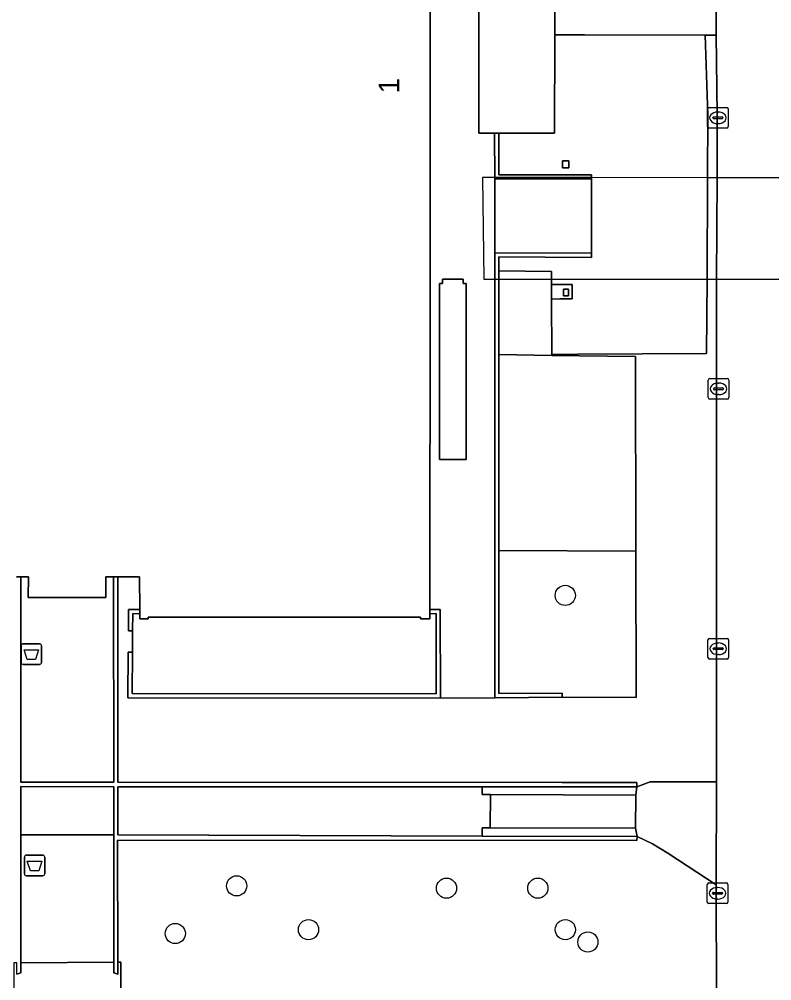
# Model space of a CAD drawing. Extents: x 161477 to 163040, y 383680 to 384871.
# Drawn here: x 161774.1 to 161810.58, y 384278.53 to 384325.12 of the extents above; entities that cross this region are included whole.
import ezdxf

# ---------------------------------------------------------------- set-up
doc = ezdxf.new("R2010")
doc.units = 0
for name, color, linetype in [('IMGEO_Afvalbak', 7, 'Continuous'), ('IMGEO_Boom', 7, 'Continuous'), ('IMGEO_Dek', 7, 'Continuous'), ('IMGEO_Erf', 7, 'Continuous'), ('IMGEO_Groenvoorziening', 7, 'Continuous'), ('IMGEO_Kolk', 7, 'Continuous'), ('IMGEO_Muur', 7, 'Continuous'), ('IMGEO_Pand', 7, 'Continuous'), ('IMGEO_Pand_nummerreeks', 7, 'Continuous'), ('IMGEO_Parkeervlak_open', 7, 'Continuous'), ('IMGEO_Pijler', 7, 'Continuous'), ('IMGEO_Rijbaan_lokaal_open', 7, 'Continuous'), ('IMGEO_Voetpad_gesloten', 7, 'Continuous'), ('IMGEO_Voetpad_op_trap', 7, 'Continuous'), ('IMGEO_Voetpad_open', 7, 'Continuous')]:
    doc.layers.add(name, color=color, linetype=linetype)

msp = doc.modelspace()

# ---------------------------------------------------------------- linework, layer by layer
at = {"layer": 'IMGEO_Afvalbak'}
for p, q in [((161774.285, 384294.86), (161775.075, 384294.86)), ((161775.075, 384294.86), (161774.285, 384294.86)), ((161774.185, 384293.96), (161774.185, 384294.76)), ((161774.185, 384294.76), (161774.185, 384293.96)), ((161775.175, 384294.76), (161775.175, 384293.96)), ((161775.175, 384293.96), (161775.175, 384294.76)), ((161775.075, 384293.86), (161774.285, 384293.86)), ((161774.285, 384293.86), (161775.075, 384293.86)), ((161774.445, 384284.62), (161775.235, 384284.62)), ((161775.235, 384284.62), (161774.445, 384284.62)), ((161774.345, 384283.72), (161774.345, 384284.52)), ((161774.345, 384284.52), (161774.345, 384283.72)), ((161775.335, 384284.52), (161775.335, 384283.72)), ((161775.335, 384283.72), (161775.335, 384284.52)), ((161775.235, 384283.62), (161774.445, 384283.62)), ((161774.445, 384283.62), (161775.235, 384283.62))]:
    msp.add_line(p, q, dxfattribs=at)
for points in [[(161774.328, 384294.574), (161775.032, 384294.574), (161774.883, 384294.104), (161774.477, 384294.104), (161774.328, 384294.574)], [(161774.488, 384284.334), (161775.192, 384284.334), (161775.043, 384283.864), (161774.637, 384283.864), (161774.488, 384284.334)]]:
    msp.add_lwpolyline(points, dxfattribs=at)
for centre, start, end in [((161774.285, 384294.76), 90, 180), ((161774.285, 384294.76), 90, 180), ((161775.075, 384294.76), 0, 90), ((161775.075, 384294.76), 360, 90), ((161774.285, 384293.96), 180, 270), ((161774.285, 384293.96), 180, 270), ((161775.075, 384293.96), 270, 0), ((161775.075, 384293.96), 270, 0), ((161774.445, 384284.52), 90, 180), ((161774.445, 384284.52), 90, 180), ((161775.235, 384284.52), 0, 90), ((161775.235, 384284.52), 360, 90), ((161774.445, 384283.72), 180, 270), ((161774.445, 384283.72), 180, 270), ((161775.235, 384283.72), 270, 0), ((161775.235, 384283.72), 270, 0)]:
    msp.add_arc(centre, 0.1, start, end, dxfattribs=at)
at = {"layer": 'IMGEO_Boom'}
for centre in [(161800.569, 384297.207), (161784.637, 384283.132), (161794.812, 384283.021), (161799.239, 384283.021), (161781.662, 384280.822), (161788.122, 384281.011), (161800.571, 384281.011), (161801.665, 384280.411)]:
    msp.add_circle(centre, 0.489, dxfattribs=at)
at = {"layer": 'IMGEO_Dek'}
msp.add_lwpolyline([(161859.88, 384317.389), (161855.377, 384317.394), (161817.96, 384317.433), (161817.483, 384317.433), (161815.892, 384317.434), (161810.287, 384317.441), (161807.922, 384317.443), (161801.84, 384317.449), (161797.149, 384317.454), (161796.557, 384317.455), (161796.614, 384312.532), (161797.345, 384312.53), (161799.896, 384312.527), (161807.923, 384312.527), (161808.422, 384312.528), (161810.306, 384312.528), (161815.872, 384312.528), (161817.492, 384312.528), (161817.958, 384312.528), (161855.375, 384312.529), (161859.867, 384312.53)], close=True, dxfattribs=at)
at = {"layer": 'IMGEO_Erf'}
msp.add_lwpolyline([(161794.302, 384296.322), (161794.005, 384296.308), (161794.005, 384296.078), (161793.545, 384296.078), (161793.545, 384296.158), (161780.347, 384296.145), (161780.346, 384296.065), (161779.936, 384296.068), (161779.938, 384296.318), (161779.598, 384296.321), (161779.592, 384295.491), (161779.584, 384294.451), (161779.569, 384292.446), (161794.316, 384292.437)], close=True, dxfattribs=at)
at = {"layer": 'IMGEO_Groenvoorziening'}
msp.add_lwpolyline([(161803.988, 384299.357), (161797.346, 384299.385), (161797.347, 384292.449), (161800.419, 384292.462), (161800.42, 384292.27), (161803.998, 384292.262)], close=True, dxfattribs=at)
msp.add_lwpolyline([(161807.898, 384277.631), (161807.882, 384283.178), (161805.547, 384284.717), (161804.8, 384285.171), (161804.047, 384285.519), (161804.034, 384285.325), (161778.862, 384285.349), (161778.872, 384279.429), (161779.026, 384279.43), (161779.027, 384277.89)], dxfattribs=at)
at = {"layer": 'IMGEO_Kolk'}
for p, q in [((161807.469, 384319.922), (161807.469, 384320.774)), ((161807.544, 384320.848), (161808.396, 384320.848)), ((161807.957, 384320.628), (161807.982, 384320.628)), ((161808.47, 384320.774), (161808.47, 384319.922)), ((161807.728, 384320.342), (161807.728, 384320.354)), ((161808.166, 384320.305), (161807.768, 384320.305)), ((161807.771, 384320.391), (161808.169, 384320.391)), ((161807.98, 384320.068), (161807.955, 384320.068)), ((161808.212, 384320.354), (161808.212, 384320.342)), ((161808.396, 384319.848), (161807.544, 384319.848)), ((161807.499, 384306.789), (161807.499, 384307.641)), ((161807.574, 384307.715), (161808.426, 384307.715)), ((161807.987, 384307.495), (161808.012, 384307.495)), ((161808.5, 384307.641), (161808.5, 384306.789)), ((161807.758, 384307.209), (161807.758, 384307.221)), ((161808.196, 384307.172), (161807.798, 384307.172)), ((161807.801, 384307.258), (161808.199, 384307.258)), ((161808.01, 384306.935), (161807.985, 384306.935)), ((161808.242, 384307.221), (161808.242, 384307.209)), ((161808.426, 384306.715), (161807.574, 384306.715)), ((161807.485, 384294.194), (161807.485, 384295.046)), ((161807.56, 384295.12), (161808.412, 384295.12)), ((161807.973, 384294.9), (161807.998, 384294.9)), ((161808.486, 384295.046), (161808.486, 384294.194)), ((161807.744, 384294.614), (161807.744, 384294.626)), ((161808.182, 384294.577), (161807.784, 384294.577)), ((161807.787, 384294.663), (161808.185, 384294.663)), ((161808.228, 384294.626), (161808.228, 384294.614)), ((161808.412, 384294.12), (161807.56, 384294.12)), ((161807.996, 384294.34), (161807.971, 384294.34)), ((161807.453, 384282.348), (161807.453, 384283.2)), ((161807.528, 384283.274), (161808.38, 384283.274)), ((161808.454, 384283.2), (161808.454, 384282.348)), ((161807.712, 384282.768), (161807.712, 384282.78)), ((161808.15, 384282.731), (161807.752, 384282.731)), ((161807.755, 384282.817), (161808.153, 384282.817)), ((161807.941, 384283.054), (161807.966, 384283.054)), ((161808.196, 384282.78), (161808.196, 384282.768)), ((161808.38, 384282.274), (161807.528, 384282.274)), ((161807.964, 384282.494), (161807.939, 384282.494))]:
    msp.add_line(p, q, dxfattribs=at)
for points in [[(161807.469, 384319.922), (161807.469, 384320.774)], [(161807.544, 384320.848), (161808.396, 384320.848)], [(161808.47, 384320.774), (161808.47, 384319.922)], [(161808.396, 384319.848), (161807.544, 384319.848)], [(161807.499, 384306.789), (161807.499, 384307.641)], [(161807.574, 384307.715), (161808.426, 384307.715)], [(161808.5, 384307.641), (161808.5, 384306.789)], [(161808.426, 384306.715), (161807.574, 384306.715)], [(161807.485, 384294.194), (161807.485, 384295.046)], [(161807.56, 384295.12), (161808.412, 384295.12)], [(161808.486, 384295.046), (161808.486, 384294.194)], [(161808.412, 384294.12), (161807.56, 384294.12)], [(161807.453, 384282.348), (161807.453, 384283.2)], [(161807.528, 384283.274), (161808.38, 384283.274)], [(161808.454, 384283.2), (161808.454, 384282.348)], [(161808.38, 384282.274), (161807.528, 384282.274)]]:
    msp.add_lwpolyline(points, dxfattribs=at)
for centre, radius, start, end in [((161807.546, 384320.772), 0.0765, 91.552, 178.448), ((161807.546, 384320.772), 0.0765, 91.552, 178.448), ((161808.394, 384320.772), 0.0765, 1.552, 88.448), ((161808.394, 384320.772), 0.0765, 1.552, 88.448), ((161807.768, 384320.351), 0.0403, 85.8775, 175.7526), ((161807.765, 384320.341), 0.0366, 178.938, 274.7102), ((161808.169, 384320.348), 0.043, 264.8664, 352.4533), ((161808.173, 384320.353), 0.0386, 1.7309, 96.639), ((161807.546, 384319.924), 0.0765, 181.552, 268.448), ((161807.546, 384319.924), 0.0765, 181.552, 268.448), ((161808.394, 384319.924), 0.0765, 271.552, 358.448), ((161808.394, 384319.924), 0.0765, 271.552, 358.448), ((161807.576, 384307.639), 0.0765, 91.552, 178.448), ((161807.576, 384307.639), 0.0765, 91.552, 178.448), ((161808.424, 384307.639), 0.0765, 1.552, 88.448), ((161808.424, 384307.639), 0.0765, 1.552, 88.448), ((161807.798, 384307.218), 0.0403, 85.8775, 175.7526), ((161807.795, 384307.208), 0.0366, 178.938, 274.7102), ((161808.199, 384307.215), 0.043, 264.8664, 352.4533), ((161808.203, 384307.22), 0.0386, 1.7309, 96.639), ((161807.576, 384306.791), 0.0765, 181.552, 268.448), ((161807.576, 384306.791), 0.0765, 181.552, 268.448), ((161808.424, 384306.791), 0.0765, 271.552, 358.448), ((161808.424, 384306.791), 0.0765, 271.552, 358.448), ((161807.562, 384295.044), 0.0765, 91.552, 178.448), ((161807.562, 384295.044), 0.0765, 91.552, 178.448), ((161808.41, 384295.044), 0.0765, 1.552, 88.448), ((161808.41, 384295.044), 0.0765, 1.552, 88.448), ((161807.784, 384294.623), 0.0403, 85.8775, 175.7526), ((161807.781, 384294.613), 0.0366, 178.938, 274.7102), ((161808.185, 384294.62), 0.043, 264.8664, 352.4533), ((161808.189, 384294.625), 0.0386, 1.7309, 96.639), ((161807.562, 384294.196), 0.0765, 181.552, 268.448), ((161807.562, 384294.196), 0.0765, 181.552, 268.448), ((161808.41, 384294.196), 0.0765, 271.552, 358.448), ((161808.41, 384294.196), 0.0765, 271.552, 358.448), ((161807.53, 384283.198), 0.0765, 91.552, 178.448), ((161807.53, 384283.198), 0.0765, 91.552, 178.448), ((161808.378, 384283.198), 0.0765, 1.552, 88.448), ((161808.378, 384283.198), 0.0765, 1.552, 88.448), ((161807.752, 384282.777), 0.0403, 85.8775, 175.7526), ((161807.749, 384282.767), 0.0366, 178.938, 274.7102), ((161808.153, 384282.774), 0.043, 264.8664, 352.4533), ((161808.157, 384282.779), 0.0386, 1.7309, 96.639), ((161807.53, 384282.35), 0.0765, 181.552, 268.448), ((161807.53, 384282.35), 0.0765, 181.552, 268.448), ((161808.378, 384282.35), 0.0765, 271.552, 358.448), ((161808.378, 384282.35), 0.0765, 271.552, 358.448)]:
    msp.add_arc(centre, radius, start, end, dxfattribs=at)
for centre, major_axis, ratio, start_param, end_param in [((161807.956, 384320.348), (-0.387, 0.002), 0.722429, 4.712389, 7.853982), ((161807.981, 384320.348), (-0.39, 0.002), 0.717154, 1.570796, 4.712389), ((161807.986, 384307.215), (-0.387, 0.002), 0.722429, 4.712389, 7.853982), ((161808.011, 384307.215), (-0.39, 0.002), 0.717154, 1.570796, 4.712389), ((161807.972, 384294.62), (-0.387, 0.002), 0.722429, 4.712389, 7.853982), ((161807.997, 384294.62), (-0.39, 0.002), 0.717154, 1.570796, 4.712389), ((161807.94, 384282.774), (-0.387, 0.002), 0.722429, 4.712389, 7.853982), ((161807.965, 384282.774), (-0.39, 0.002), 0.717154, 1.570796, 4.712389)]:
    msp.add_ellipse(centre, major_axis=major_axis, ratio=ratio, start_param=start_param, end_param=end_param, dxfattribs=at)
at = {"layer": 'IMGEO_Muur'}
for points in [[(161801.84, 384317.591), (161797.345, 384317.591), (161797.343, 384319.61), (161797.293, 384319.61), (161797.163, 384319.61), (161797.143, 384319.61), (161797.149, 384317.391), (161797.789, 384317.393), (161799.92, 384317.392), (161801.84, 384317.391), (161801.84, 384317.449)], [(161800.419, 384292.462), (161797.347, 384292.449), (161797.346, 384299.385), (161797.345, 384308.876), (161797.345, 384312.527), (161797.345, 384312.94), (161797.345, 384313.606), (161801.833, 384313.584), (161801.834, 384313.784), (161797.153, 384313.81), (161797.153, 384312.527), (161797.154, 384292.246), (161800.42, 384292.27)], [(161794.005, 384296.528), (161794.005, 384296.308), (161794.302, 384296.322), (161794.316, 384292.437), (161779.569, 384292.446), (161779.584, 384294.451), (161779.384, 384294.453), (161779.368, 384292.243), (161794.518, 384292.229), (161794.505, 384296.529)], [(161779.399, 384296.523), (161779.392, 384295.493), (161779.592, 384295.491), (161779.598, 384296.321), (161779.938, 384296.318), (161779.949, 384296.519)]]:
    msp.add_lwpolyline(points, close=True, dxfattribs=at)
for points in [[(161774.172, 384285.606), (161774.172, 384287.756), (161774.172, 384287.94), (161778.675, 384287.927), (161778.675, 384287.788), (161778.675, 384285.6), (161778.675, 384285.349), (161778.674, 384279.439), (161778.674, 384278.921), (161778.872, 384278.853), (161778.872, 384279.429), (161778.862, 384285.349), (161804.034, 384285.325), (161804.047, 384285.519), (161796.534, 384285.535), (161778.872, 384285.6), (161778.872, 384287.926), (161796.542, 384287.937), (161804.042, 384287.932), (161804.04, 384288.14), (161800.42, 384288.142), (161778.872, 384288.151), (161778.873, 384298.105), (161778.673, 384298.106), (161778.675, 384288.151), (161774.172, 384288.153), (161774.169, 384298.113), (161773.969, 384298.113)], [(161773.975, 384278.852), (161774.17, 384278.92), (161774.17, 384279.4), (161774.172, 384285.353), (161774.172, 384285.606)]]:
    msp.add_lwpolyline(points, dxfattribs=at)
at = {"layer": 'IMGEO_Pand'}
msp.add_lwpolyline([(161773.969, 384298.113), (161774.169, 384298.113), (161774.538, 384298.112), (161774.536, 384297.112), (161778.295, 384297.106), (161778.297, 384298.106), (161778.673, 384298.106), (161778.873, 384298.105), (161779.927, 384298.104), (161779.949, 384296.519), (161779.938, 384296.318), (161779.936, 384296.068), (161780.346, 384296.065), (161780.347, 384296.145), (161793.545, 384296.158), (161793.545, 384296.078), (161794.005, 384296.078), (161794.005, 384296.308), (161794.005, 384296.528), (161794.014, 384312.527), (161794.019, 384322.699), (161794.021, 384323.884), (161794.05, 384339.66)], dxfattribs=at)
msp.add_lwpolyline([(161800.061, 384324.375), (161800.065, 384326.568), (161799.065, 384326.565), (161797.324, 384326.559), (161797.124, 384326.558), (161796.384, 384326.556), (161796.384, 384323.884), (161796.383, 384319.61), (161796.612, 384319.61), (161797.143, 384319.61), (161797.163, 384319.61), (161797.293, 384319.61), (161797.343, 384319.61), (161797.393, 384319.61), (161797.493, 384319.61), (161800.053, 384319.61)], close=True, dxfattribs=at)
at = {"layer": 'IMGEO_Parkeervlak_open'}
msp.add_lwpolyline([(161803.974, 384308.789), (161799.914, 384308.823), (161797.345, 384308.876), (161797.346, 384299.385), (161803.988, 384299.357)], close=True, dxfattribs=at)
at = {"layer": 'IMGEO_Pijler'}
for points in [[(161800.741, 384318.261), (161800.431, 384318.262), (161800.43, 384317.922), (161800.74, 384317.921)], [(161800.719, 384312.05), (161800.479, 384312.049), (161800.48, 384311.719), (161800.72, 384311.72)]]:
    msp.add_lwpolyline(points, close=True, dxfattribs=at)
at = {"layer": 'IMGEO_Rijbaan_lokaal_open'}
msp.add_lwpolyline([(161807.864, 384334.408), (161807.877, 384324.354), (161807.935, 384320.508), (161807.925, 384317.443), (161807.908, 384312.527), (161807.894, 384308.423), (161807.907, 384299.209), (161807.894, 384288.165), (161807.882, 384283.178), (161807.898, 384277.631), (161807.859, 384276.931), (161807.864, 384268.831), (161807.865, 384262.928), (161807.874, 384261.983), (161807.834, 384257.732), (161807.858, 384256.855), (161807.863, 384256.708), (161813.986, 384256.731)], dxfattribs=at)
at = {"layer": 'IMGEO_Voetpad_gesloten'}
msp.add_lwpolyline([(161855.377, 384317.394), (161817.96, 384317.433), (161817.483, 384317.433), (161815.892, 384317.434), (161810.287, 384317.441), (161807.925, 384317.443), (161807.464, 384317.443), (161801.84, 384317.449), (161797.149, 384317.454), (161796.557, 384317.455), (161796.614, 384312.532), (161797.345, 384312.53), (161799.896, 384312.527), (161807.908, 384312.527), (161810.306, 384312.528), (161815.872, 384312.528), (161817.492, 384312.528), (161817.958, 384312.528), (161855.375, 384312.529)], dxfattribs=at)
for points in [[(161796.542, 384287.937), (161796.54, 384287.555), (161796.94, 384287.553), (161803.986, 384287.526), (161804.042, 384287.932)], [(161804.047, 384285.519), (161803.976, 384285.925), (161796.935, 384285.936), (161796.535, 384285.936), (161796.534, 384285.535)]]:
    msp.add_lwpolyline(points, close=True, dxfattribs=at)
at = {"layer": 'IMGEO_Voetpad_op_trap'}
for points in [[(161801.84, 384317.391), (161799.92, 384317.392), (161797.789, 384317.393), (161797.149, 384317.391), (161797.153, 384313.81), (161801.834, 384313.784)], [(161795.765, 384312.323), (161795.615, 384312.323), (161795.615, 384312.533), (161794.619, 384312.527), (161794.619, 384312.317), (161794.469, 384312.317), (161794.474, 384303.786), (161795.77, 384303.792)], [(161778.673, 384298.106), (161778.297, 384298.106), (161778.295, 384297.106), (161774.536, 384297.112), (161774.538, 384298.112), (161774.169, 384298.113), (161774.172, 384288.153), (161778.675, 384288.151)], [(161778.675, 384287.788), (161778.675, 384287.927), (161774.172, 384287.94), (161774.172, 384287.756), (161774.172, 384285.606), (161778.675, 384285.6)], [(161778.675, 384285.349), (161778.675, 384285.6), (161774.172, 384285.606), (161774.172, 384285.353), (161774.17, 384279.4), (161778.674, 384279.439)]]:
    msp.add_lwpolyline(points, close=True, dxfattribs=at)
at = {"layer": 'IMGEO_Voetpad_open'}
for points in [[(161796.384, 384323.884), (161796.384, 384326.556), (161797.124, 384326.558), (161797.155, 384343.925), (161794.591, 384343.938), (161794.57, 384339.658), (161794.05, 384339.66), (161794.021, 384323.884), (161794.019, 384322.699), (161794.014, 384312.527), (161794.005, 384296.528), (161794.505, 384296.529), (161794.518, 384292.229), (161797.154, 384292.246), (161797.153, 384312.527), (161797.153, 384313.81), (161797.149, 384317.391), (161797.143, 384319.61), (161796.612, 384319.61), (161796.383, 384319.61)], [(161807.864, 384334.408), (161807.912, 384342.77), (161807.911, 384343.752), (161803.991, 384343.777), (161803.971, 384337.086), (161803.967, 384335.774), (161797.35, 384335.706), (161797.34, 384332.207), (161799.035, 384332.237), (161799.065, 384326.565), (161800.065, 384326.568), (161800.061, 384324.375), (161801.506, 384324.371), (161807.35, 384324.357), (161807.877, 384324.354)], [(161807.907, 384299.209), (161807.894, 384308.423), (161807.908, 384312.527), (161807.925, 384317.443), (161807.935, 384320.508), (161807.877, 384324.354), (161807.35, 384324.357), (161807.478, 384320.481), (161807.464, 384317.443), (161807.44, 384312.527), (161807.423, 384308.935), (161801.183, 384308.889), (161799.914, 384308.879), (161799.914, 384308.823), (161803.974, 384308.789), (161803.988, 384299.357), (161803.998, 384292.262), (161800.42, 384292.27), (161797.154, 384292.246), (161794.518, 384292.229), (161779.368, 384292.243), (161779.384, 384294.453), (161779.584, 384294.451), (161779.592, 384295.491), (161779.392, 384295.493), (161779.399, 384296.523), (161779.949, 384296.519), (161779.927, 384298.104), (161778.873, 384298.105), (161778.872, 384288.151), (161800.42, 384288.142), (161804.04, 384288.14), (161804.042, 384287.932), (161804.684, 384288.178), (161807.894, 384288.165)], [(161807.464, 384317.443), (161807.478, 384320.481), (161807.35, 384324.357), (161801.506, 384324.371), (161800.061, 384324.375), (161800.053, 384319.61), (161797.493, 384319.61), (161797.393, 384319.61), (161797.343, 384319.61), (161797.345, 384317.591), (161801.84, 384317.591), (161801.84, 384317.449), (161801.84, 384317.391), (161801.834, 384313.784), (161801.833, 384313.584), (161797.345, 384313.606), (161797.345, 384312.94), (161799.894, 384312.896), (161799.896, 384312.527), (161799.897, 384312.266), (161800.297, 384312.268), (161800.897, 384312.271), (161800.901, 384311.571), (161800.301, 384311.568), (161799.901, 384311.566), (161799.914, 384308.879), (161801.183, 384308.889), (161807.423, 384308.935), (161807.44, 384312.527)], [(161800.74, 384317.921), (161800.43, 384317.922), (161800.431, 384318.262), (161800.741, 384318.261)], [(161795.615, 384312.323), (161795.765, 384312.323), (161795.77, 384303.792), (161794.474, 384303.786), (161794.469, 384312.317), (161794.619, 384312.317), (161794.619, 384312.527), (161795.615, 384312.533)], [(161799.901, 384311.566), (161799.897, 384312.266), (161799.896, 384312.527), (161799.894, 384312.896), (161797.345, 384312.94), (161797.345, 384312.527), (161797.345, 384308.876), (161799.914, 384308.823), (161799.914, 384308.879)], [(161800.897, 384312.271), (161800.297, 384312.268), (161799.897, 384312.266), (161799.901, 384311.566), (161800.301, 384311.568), (161800.901, 384311.571)], [(161800.479, 384312.049), (161800.719, 384312.05), (161800.72, 384311.72), (161800.48, 384311.719)], [(161778.872, 384287.926), (161778.872, 384285.6), (161796.534, 384285.535), (161796.535, 384285.936), (161796.935, 384285.936), (161796.94, 384287.553), (161796.54, 384287.555), (161796.542, 384287.937)], [(161807.894, 384288.165), (161804.684, 384288.178), (161804.042, 384287.932), (161803.986, 384287.526), (161803.976, 384285.925), (161804.047, 384285.519), (161804.8, 384285.171), (161805.547, 384284.717), (161807.882, 384283.178)], [(161803.976, 384285.925), (161803.986, 384287.526), (161796.94, 384287.553), (161796.935, 384285.936)], [(161779.026, 384279.43), (161778.872, 384279.429), (161778.872, 384278.853), (161778.674, 384278.921), (161778.674, 384279.439), (161774.17, 384279.4), (161774.17, 384278.92), (161773.975, 384278.852), (161773.975, 384279.41), (161773.828, 384279.409), (161773.834, 384278.174), (161773.842, 384277.884), (161779.027, 384277.89)]]:
    msp.add_lwpolyline(points, close=True, dxfattribs=at)

# ---------------------------------------------------------------- texts
at = {"layer": 'IMGEO_Pand_nummerreeks'}
msp.add_text('1', height=1, rotation=89.9716, dxfattribs=at).set_placement((161792.519, 384321.534))

doc.saveas('drawing.dxf')
